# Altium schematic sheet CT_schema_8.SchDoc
size 371 x 336 mm
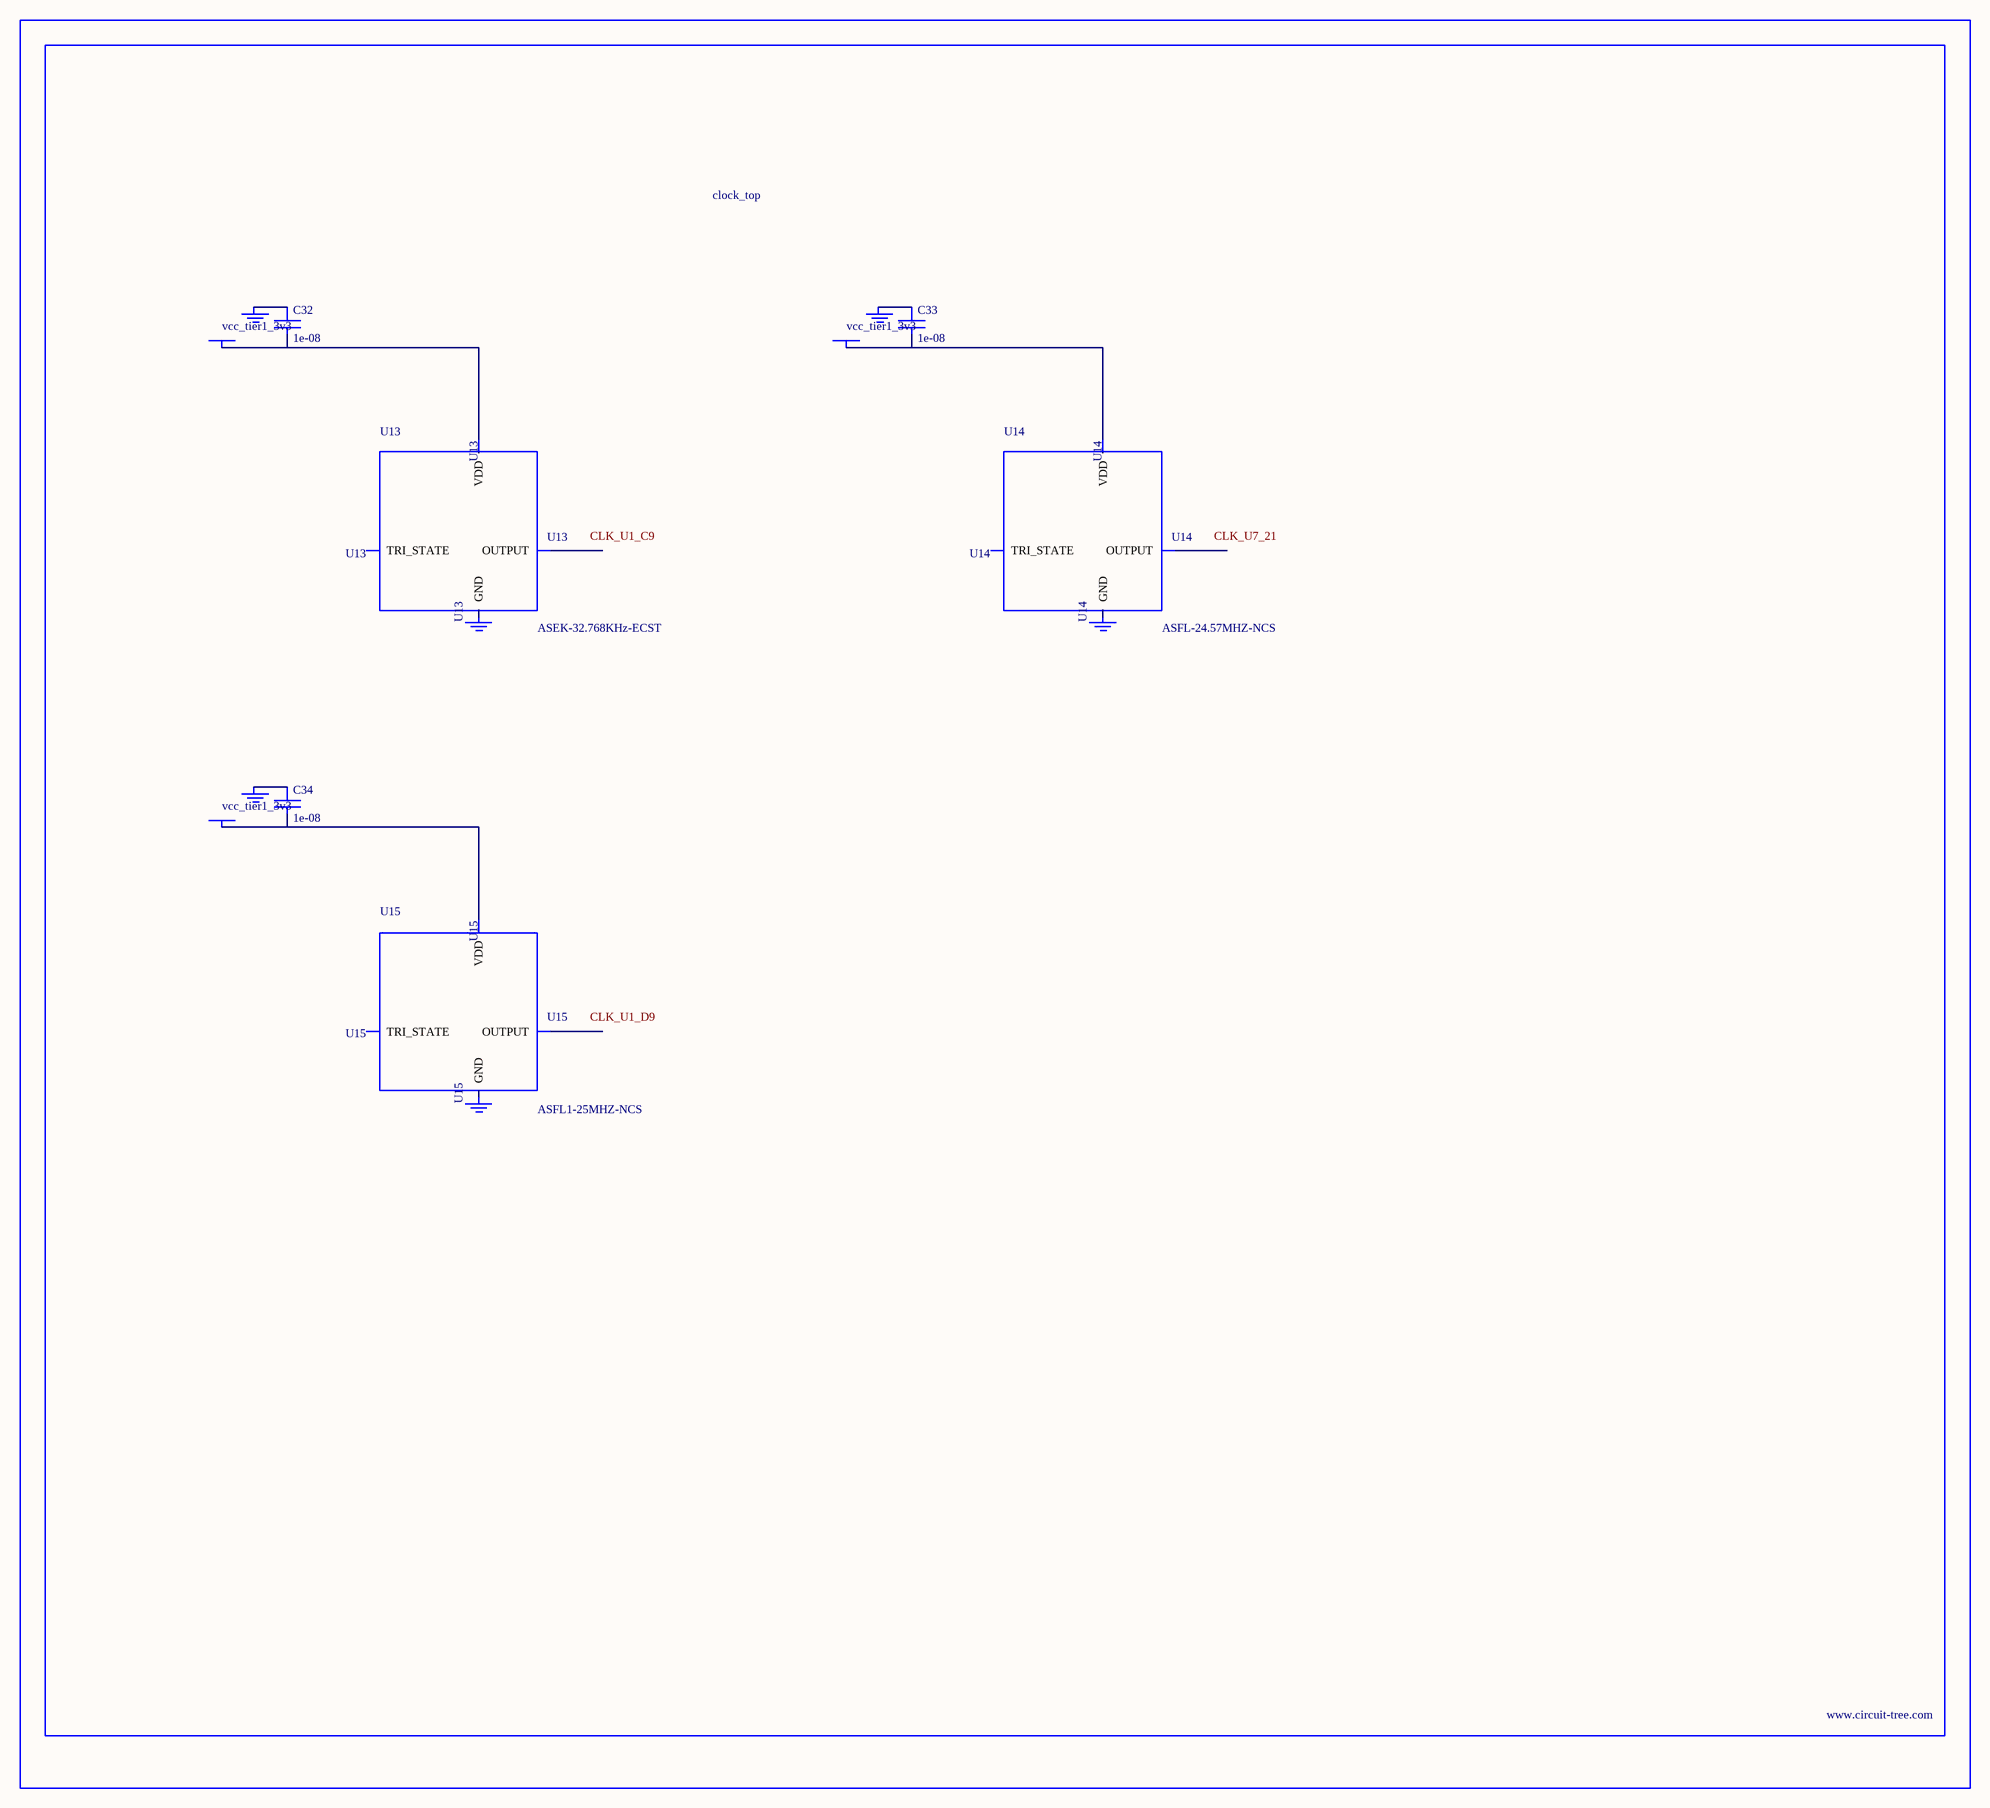
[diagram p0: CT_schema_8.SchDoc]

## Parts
BORDER7  (no value)
C32  1e-08  [C0402]
C33  1e-08  [C0402]
C34  1e-08  [C0402]
GND_INSTANCE_7_0  (no value)
GND_INSTANCE_7_1  (no value)
GND_INSTANCE_7_2  (no value)
GND_INSTANCE_7_3  (no value)
GND_INSTANCE_7_4  (no value)
GND_INSTANCE_7_5  (no value)
POWER_INSTANCE_7_0  vcc_tier1_3v3
POWER_INSTANCE_7_1  vcc_tier1_3v3
POWER_INSTANCE_7_2  vcc_tier1_3v3
U13  ASEK-32.768KHz-ECST  [ASEK]
U14  ASFL-24.57MHZ-NCS  [ASFL1]
U15  ASFL1-25MHZ-NCS  [ASFL1]

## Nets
NetC32_1: C32.1 GND_INSTANCE_7_0.0(GND)
NetC32_2: C32.2 POWER_INSTANCE_7_0.0(PWR) U13.4(VDD)
NetC33_1: C33.1 GND_INSTANCE_7_2.0(GND)
NetC33_2: C33.2 POWER_INSTANCE_7_1.0(PWR) U14.4(VDD)
NetC34_1: C34.1 GND_INSTANCE_7_4.0(GND)
NetC34_2: C34.2 POWER_INSTANCE_7_2.0(PWR) U15.4(VDD)

Not connected (* = marked no-connect by the designer): GND_INSTANCE_7_1 0(GND); GND_INSTANCE_7_3 0(GND); GND_INSTANCE_7_5 0(GND); U13 1(TRI_STATE) 2(GND) 3(OUTPUT); U14 1(TRI_STATE) 2(GND) 3(OUTPUT); U15 1(TRI_STATE) 2(GND) 3(OUTPUT)

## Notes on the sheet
- Labels drawn without touching a wire or pin: CLK_U1_C9, CLK_U1_D9, CLK_U7_21

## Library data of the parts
BORDER7 = BORDER_PAGE7
C32-C34 = C0402C103K3RAC
GND_INSTANCE_7_0-GND_INSTANCE_7_5 = GND
POWER_INSTANCE_7_0-POWER_INSTANCE_7_2 = PWR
